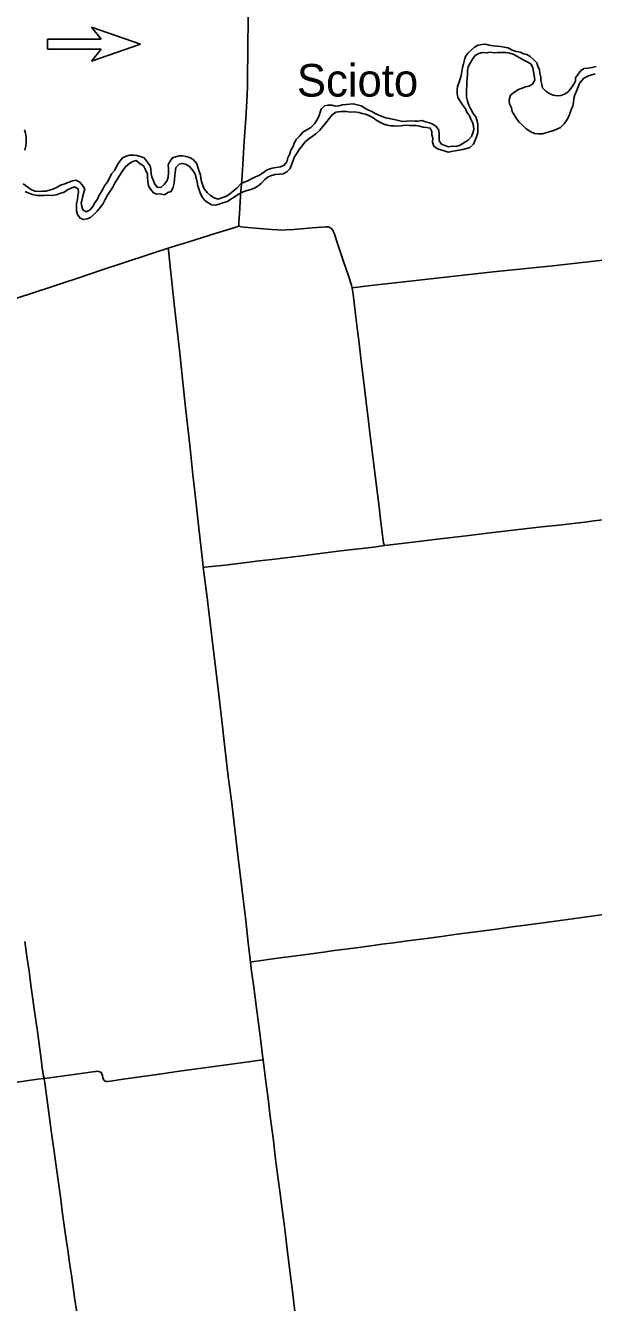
# Model space of a CAD drawing. Extents: x 0 to 680, y 0 to 440.
# Drawn here: x 190.2 to 248.2, y 233.7 to 364.2 of the extents above; entities that cross this region are included whole.
import ezdxf

# ---------------------------------------------------------------- set-up
doc = ezdxf.new("R2010")
doc.units = 0
for name, color, linetype in [('GM_X_County_Road', 7, 'Continuous'), ('GM_X_Major_River', 7, 'Continuous'), ('GM_X_Major_River_Text', 7, 'Continuous'), ('GM_X_Township_Road', 7, 'Continuous'), ('PM_P_Cells', 7, 'Continuous')]:
    doc.layers.add(name, color=color, linetype=linetype)

msp = doc.modelspace()

# ---------------------------------------------------------------- linework, layer by layer
at = {"layer": 'GM_X_County_Road'}
for points in [[(212.24, 347.98), (212.27, 348.35), (212.37, 349.99), (212.53, 352.39), (212.69, 354.68), (212.83, 357.08), (212.86, 358.06), (212.91, 362.44), (212.93, 364.41), (212.94, 365.18)], [(211.97, 343.69), (211.98, 344.09), (212.04, 344.97), (212.12, 346.17), (212.19, 347.26), (212.24, 347.98)], [(204.77, 341.45), (205.49, 341.69), (206.75, 342.07), (209.67, 342.98), (211.35, 343.49), (211.66, 343.59), (211.97, 343.69)], [(223.55, 337.4), (223.52, 337.53), (223.47, 337.68), (223.17, 338.62), (222.64, 340.17), (222.12, 341.73), (221.71, 342.97), (221.63, 343.17), (221.58, 343.27), (221.52, 343.36), (221.45, 343.44), (221.37, 343.5), (221.28, 343.55), (221.19, 343.59), (221.09, 343.61), (220.98, 343.63), (220.88, 343.63), (220.44, 343.59), (219.46, 343.51), (217.61, 343.36), (216.84, 343.31), (216.4, 343.3), (215.96, 343.32), (215.31, 343.36), (213.67, 343.5), (212.47, 343.6), (212.25, 343.63), (211.97, 343.69)], [(184.22, 333.58), (184.26, 333.59), (184.3, 333.6), (184.32, 333.62), (184.42, 333.68), (184.59, 333.82), (185.03, 334.15), (185.49, 334.45), (185.86, 334.68), (186.91, 335.27), (187.58, 335.63), (187.97, 335.83), (188.37, 336), (188.78, 336.15), (189.81, 336.51), (190.54, 336.75), (191.26, 336.99), (192.62, 337.43), (193.86, 337.84), (195.52, 338.39), (198.12, 339.25), (199.99, 339.87), (203.1, 340.9), (204.77, 341.45)], [(208.33, 308.82), (208.28, 309.25), (207.9, 312.84), (207.45, 316.87), (207.29, 318.28), (206.99, 321), (206.5, 325.46), (205.9, 331.01), (205.41, 335.46), (205, 339.27), (204.79, 341.23), (204.77, 341.45)], [(223.55, 337.4), (223.83, 337.44), (225.46, 337.64), (230.35, 338.19), (237.96, 339.02), (244.06, 339.65), (249.17, 340.21), (250.6, 340.37)], [(226.87, 311.05), (226.77, 311.33), (226.6, 312.63), (226.43, 314.04), (226.3, 315.02), (226.01, 317.4), (225.63, 320.44), (225.41, 322.29), (225.15, 324.35), (224.95, 325.98), (224.74, 327.71), (224.48, 329.89), (224.26, 331.73), (224.1, 333.03), (223.91, 334.66), (223.66, 336.73), (223.6, 337.16), (223.56, 337.37), (223.55, 337.4)], [(226.87, 311.05), (229.8, 311.41), (230.34, 311.47), (230.88, 311.53), (231.97, 311.67), (235.22, 312.06), (237.37, 312.32), (240.87, 312.73), (242.94, 312.96), (244.68, 313.16), (246.41, 313.36), (247.34, 313.46), (248.26, 313.57), (251.09, 313.89), (252.82, 314.1), (253.56, 314.18)], [(208.33, 308.82), (208.52, 308.84), (208.84, 308.87), (210.58, 309.06), (211.67, 309.2), (212.75, 309.33), (214.06, 309.49), (215.36, 309.65), (218.72, 310.06), (220.79, 310.32), (222.41, 310.51), (225.78, 310.91), (226.87, 311.05)], [(213.18, 268.5), (212.94, 270.47), (212.69, 272.75), (212.44, 274.68), (211.87, 279.42), (211.39, 283.54), (211.25, 284.74), (210.9, 287.45), (210.42, 291.62), (210.3, 292.61), (209.78, 296.98), (209.08, 302.85), (208.73, 305.74), (208.42, 308.06), (208.33, 308.82)], [(213.18, 268.5), (213.5, 268.55), (214.04, 268.63), (215.45, 268.82), (216.75, 268.99), (219.13, 269.32), (220.86, 269.55), (221.73, 269.67), (222.6, 269.79), (224.22, 270), (225.95, 270.24), (226.6, 270.33), (227.79, 270.48), (229.2, 270.66), (231.15, 270.91), (232.45, 271.09), (234.29, 271.34), (235.92, 271.56), (238.3, 271.88), (239.92, 272.1), (241.01, 272.25), (243.06, 272.52), (244.58, 272.72), (247.07, 273.06), (249.99, 273.45)], [(214.45, 258.52), (214.39, 258.96), (214.14, 260.96), (213.7, 264.29), (213.53, 265.69), (213.28, 267.59), (213.18, 268.5)], [(192.07, 256.61), (192.64, 256.69), (194.6, 256.94), (196.33, 257.18), (197.31, 257.33), (197.41, 257.34), (197.53, 257.35), (197.65, 257.33), (197.76, 257.3), (197.86, 257.24), (197.94, 257.16), (197.99, 257.06), (198.03, 256.95), (198.09, 256.63), (198.13, 256.53), (198.18, 256.44), (198.25, 256.37), (198.34, 256.33), (198.44, 256.31), (198.54, 256.31), (198.87, 256.35), (200.16, 256.55), (201.9, 256.78), (203.63, 257.02), (205.69, 257.31), (208.95, 257.76), (212.96, 258.31), (214.15, 258.48), (214.45, 258.52)], [(218.73, 224.62), (218.7, 224.88), (218.22, 228.68), (217.91, 231.07), (217.41, 235.14), (217.28, 236.17), (216.98, 238.6), (216.66, 241.2), (216.47, 242.75), (216.3, 244.05), (216.15, 245.11), (215.96, 246.55), (215.7, 248.65), (215.5, 250.29), (215.19, 252.71), (214.96, 254.56), (214.7, 256.54), (214.45, 258.52)], [(188.85, 256.17), (191.45, 256.53), (192.07, 256.61)]]:
    msp.add_lwpolyline(points, dxfattribs=at)
at = {"layer": 'GM_X_Major_River'}
for points in [[(238.35, 362.08), (237.97, 362.12), (237.54, 362.2), (237.17, 362.28), (236.82, 362.25), (236.43, 362.17), (236.04, 361.97), (235.71, 361.68), (235.37, 361.38), (235.13, 361.03), (235.02, 360.67), (234.92, 360.28), (234.82, 359.92), (234.75, 359.49), (234.7, 359.08), (234.5, 358.39), (234.32, 357.96), (234.28, 357.62), (234.28, 357.23), (234.34, 356.83), (234.58, 356.48), (234.83, 356.08), (235.13, 355.69), (235.27, 355.34), (235.56, 354.96), (235.67, 354.63), (235.85, 354.29), (235.95, 353.95), (235.97, 353.58), (235.9, 353.22), (235.76, 352.87), (235.42, 352.48), (234.95, 352.21), (234.6, 351.96), (234.17, 351.83), (233.77, 351.85), (233.39, 351.8), (233.02, 351.94), (232.68, 352.07), (232.43, 352.41), (232.44, 352.77), (232.45, 353.1), (232.41, 353.5), (232.13, 353.88), (231.79, 354.1), (231.45, 354.26), (231.06, 354.36), (230.7, 354.48), (230.3, 354.42), (229.97, 354.43), (229.51, 354.45), (229.1, 354.43), (228.7, 354.38), (228.3, 354.48), (227.86, 354.58), (227.35, 354.7), (227, 354.77), (226.62, 354.9), (226.28, 355.04), (225.92, 355.19), (225.58, 355.41), (225.23, 355.56), (224.85, 355.74), (224.48, 355.97), (224.05, 356.09), (223.65, 356.19), (223.29, 356.15), (222.95, 356.13), (222.55, 356.1), (222.18, 356), (221.84, 355.96), (221.48, 356.04), (221.09, 356.06), (220.73, 355.98), (220.4, 355.64), (220.14, 354.88), (219.96, 354.51), (219.72, 354.14), (219.32, 353.76), (218.93, 353.55), (218.51, 353.3), (218.21, 352.92), (217.87, 352.59), (217.62, 352.18), (217.52, 351.82), (217.28, 351.45), (217.2, 351.09), (216.98, 350.66), (216.88, 350.28), (216.62, 349.94), (216.22, 349.75), (215.79, 349.69), (215.39, 349.63), (214.88, 349.46), (214.38, 349.1), (214.02, 348.87), (213.68, 348.72), (213.26, 348.53), (212.9, 348.32), (212.52, 348.2), (212.13, 347.97)], [(229.37, 353.98), (230.08, 353.97), (230.43, 353.9), (230.81, 353.81), (231.16, 353.79), (231.54, 353.72), (231.68, 353.37), (231.71, 353.02), (231.79, 352.69), (231.76, 352.27), (231.9, 351.88), (232.26, 351.61), (232.95, 351.38), (233.37, 351.24), (233.71, 351.32), (234.07, 351.38), (234.44, 351.45), (234.85, 351.53), (235.23, 351.63), (235.58, 351.74), (235.94, 352.06), (236.13, 352.47), (236.27, 352.83), (236.41, 353.24), (236.4, 353.65), (236.38, 354.07), (236.32, 354.43), (236.19, 354.86), (235.93, 355.21), (235.66, 355.71), (235.48, 356.05), (235.34, 356.48), (235.24, 356.87), (235.23, 357.21), (235.25, 357.68), (235.26, 358.03), (235.28, 358.36), (235.3, 358.78), (235.33, 359.2), (235.34, 359.61), (235.42, 359.96), (235.6, 360.36), (235.85, 360.77), (236.14, 361.13), (236.5, 361.32), (236.88, 361.44), (237.33, 361.4), (237.66, 361.47), (238.06, 361.41), (238.4, 361.44), (238.87, 361.45), (239.25, 361.43), (239.65, 361.37), (240, 361.25), (240.37, 361.05), (240.79, 360.81), (241.16, 360.62), (241.52, 360.45), (241.86, 360.23), (242.03, 359.86), (242.08, 359.51), (242.15, 359.12), (242.22, 358.61), (241.98, 358.21), (241.61, 358.01), (241.28, 357.92), (240.93, 357.8), (240.55, 357.66), (240.19, 357.43), (239.74, 357.07), (239.6, 356.61), (239.63, 356.19), (239.83, 355.78), (239.9, 355.4), (240.12, 355.06), (240.32, 354.71), (240.62, 354.32), (241, 353.97), (241.35, 353.64), (241.8, 353.34), (242.2, 353.17), (242.59, 353.14), (243, 353.13), (243.36, 353.23), (243.79, 353.37), (244.17, 353.47), (244.52, 353.64), (244.85, 353.79), (245.22, 354.14), (245.45, 354.48), (245.65, 354.84), (245.81, 355.22), (245.92, 355.58), (246.09, 355.98), (246.18, 356.34), (246.21, 356.73), (246.3, 357.1), (246.48, 357.5), (246.64, 357.92), (246.82, 358.33), (247.21, 358.8)], [(248.47, 359.99), (248.05, 359.89), (247.64, 359.83), (247.26, 359.8), (246.92, 359.58), (246.66, 359.21), (246.39, 358.84), (246.37, 358.5), (246.13, 358.1), (245.91, 357.75), (245.59, 357.38), (245.26, 357.17), (244.87, 357.03), (244.49, 357.01), (244.11, 357.06), (243.76, 357.22), (243.33, 357.5), (243.02, 357.83), (242.94, 358.17), (242.82, 358.57), (242.82, 358.91), (242.74, 359.31), (242.69, 359.66), (242.53, 360.04), (242.41, 360.37), (242.1, 360.72), (241.76, 361.02), (241.41, 361.23), (241.07, 361.3), (240.71, 361.48), (240.32, 361.54), (239.9, 361.68), (239.49, 361.9), (239.07, 361.98), (238.7, 362.04), (238.35, 362.08)], [(247.21, 358.8), (247.7, 359.05), (248.05, 359.17), (248.4, 359.24)], [(198.55, 346.87), (198.81, 347.27), (199.09, 347.69), (199.35, 348.15), (199.58, 348.54), (199.8, 348.91), (200.03, 349.26), (200.4, 349.75), (200.82, 350.12), (201.16, 350.29), (201.49, 350.39), (201.88, 350.06), (202.22, 349.84), (202.43, 349.45), (202.63, 349.02), (202.65, 348.66), (202.69, 348.24), (202.75, 347.82), (202.95, 347.48), (203.24, 347.09), (203.59, 346.97), (203.93, 346.99), (204.37, 346.91), (204.71, 347.14), (205.06, 347.24), (205.28, 347.68), (205.38, 348.09), (205.41, 348.49), (205.47, 349.19), (205.55, 349.69), (205.89, 350.02), (206.23, 350.1), (206.61, 350), (206.97, 349.77), (207.27, 349.37), (207.5, 349.01), (207.62, 348.62), (207.71, 348.19), (207.79, 347.83), (207.88, 347.49), (208.02, 347.1), (208.21, 346.71), (208.5, 346.32), (208.85, 346.07), (209.23, 345.87), (209.58, 345.83), (209.98, 345.93), (210.34, 346.06), (210.81, 346.21), (211.17, 346.45), (211.51, 346.64), (211.94, 346.97), (212.43, 347.2), (212.82, 347.33), (213.21, 347.43), (213.58, 347.56), (213.96, 347.82), (214.3, 348.07), (214.62, 348.46), (214.96, 348.74), (215.3, 348.88), (215.69, 348.97), (216.12, 349), (216.5, 349.05), (216.87, 349.24), (217.22, 349.58), (217.37, 349.97), (217.5, 350.33), (217.67, 350.77), (217.93, 351.18), (218.15, 351.52), (218.42, 351.88), (218.76, 352.3), (219.14, 352.6), (219.48, 352.85), (219.85, 353.11), (220.23, 353.45), (220.55, 353.87), (220.86, 354.26), (221.24, 354.72), (221.51, 355.07), (221.89, 355.33), (222.44, 355.42), (222.93, 355.4), (223.39, 355.35), (223.8, 355.36), (224.23, 355.3), (224.57, 355.22), (224.93, 355.12), (225.33, 354.96), (225.69, 354.76), (226.07, 354.5), (226.44, 354.27), (226.78, 354.1), (227.13, 354.01), (227.49, 353.95), (227.85, 353.93), (228.18, 353.92), (228.57, 353.94), (229.01, 354.01), (229.37, 353.98)], [(190.12, 351.46), (190.2, 351.9), (190.25, 352.34), (190.24, 352.78), (190.19, 353.18), (190.08, 353.52)], [(212.13, 347.97), (211.77, 347.57), (211.4, 347.26), (211.05, 347), (210.7, 346.76), (210.24, 346.57), (209.85, 346.44), (209.47, 346.57), (209.08, 346.83), (208.74, 347.13), (208.44, 347.5), (208.29, 347.86), (208.16, 348.24), (208.1, 348.57), (208.05, 348.93), (207.92, 349.28), (207.8, 349.71), (207.67, 350.07), (207.38, 350.44), (207.02, 350.66), (206.59, 350.81), (206.21, 350.89), (205.87, 350.88), (205.52, 350.78), (205.18, 350.69), (204.94, 350.29), (204.77, 349.95), (204.79, 349.56), (204.78, 349.13), (204.74, 348.71), (204.65, 348.36), (204.39, 347.99), (204.04, 347.67), (203.68, 347.64), (203.39, 347.98), (203.25, 348.32), (203.07, 348.72), (203.03, 349.09), (202.99, 349.54), (202.91, 349.87), (202.6, 350.26), (202.3, 350.67), (201.93, 350.8), (201.56, 350.9), (201.2, 350.94), (200.85, 350.95), (200.47, 350.83), (200.1, 350.67), (199.72, 350.21), (199.5, 349.86), (199.3, 349.42), (198.98, 349.04), (198.75, 348.6), (198.55, 348.23), (198.25, 347.81), (198.03, 347.39), (197.68, 346.8), (197.52, 346.46), (197.26, 346.06), (197.07, 345.7), (196.77, 345.35), (196.39, 345.17), (196.04, 345.36), (195.93, 345.7), (195.87, 346.06), (195.96, 346.42), (196.05, 346.78), (196.14, 347.12), (196.23, 347.5), (196.02, 347.83), (195.74, 348.19), (195.33, 348.39), (194.99, 348.33), (194.53, 348.15), (194.09, 348), (193.75, 347.87), (193.41, 347.66), (192.97, 347.48), (192.63, 347.37), (192.27, 347.27), (191.91, 347.27), (191.56, 347.22), (191.18, 347.27), (190.78, 347.42), (189.93, 348.01)], [(190.15, 347.22), (190.53, 347.08), (190.9, 346.93), (191.34, 346.83), (191.73, 346.81), (192.09, 346.84), (192.51, 346.87), (192.95, 346.84), (193.31, 346.9), (193.7, 347.02), (194.11, 347.17), (194.46, 347.4), (194.83, 347.59), (195.19, 347.7), (195.55, 347.52), (195.58, 347.16), (195.52, 346.8), (195.49, 346.42), (195.39, 345.99), (195.37, 345.65), (195.38, 345.25), (195.49, 344.89), (195.76, 344.51), (196.11, 344.36), (196.47, 344.43), (196.81, 344.57), (197.17, 344.9), (197.51, 345.22), (197.85, 345.64), (198.12, 346.01), (198.32, 346.42), (198.55, 346.87)]]:
    msp.add_lwpolyline(points, dxfattribs=at)
at = {"layer": 'GM_X_Township_Road'}
for points in [[(192.07, 256.61), (192.07, 256.66), (192.03, 256.85), (191.89, 257.71), (191.78, 258.58), (191.39, 261.4), (191.16, 263.02), (190.73, 266.16), (190.54, 267.57), (190.32, 269.08), (190.11, 270.6)], [(195.88, 229.33), (195.86, 229.48), (195.75, 230.34), (195.65, 230.99), (195.54, 231.86), (195.38, 232.94), (195.19, 234.24), (194.86, 236.51), (194.77, 237.14), (194.65, 238.01), (194.53, 238.88), (194.3, 240.41), (193.97, 242.79), (193.74, 244.52), (193.57, 245.71), (193.3, 247.66), (193.06, 249.4), (192.83, 251.02), (192.48, 253.62), (192.17, 255.9), (192.07, 256.61)]]:
    msp.add_lwpolyline(points, dxfattribs=at)
at = {"layer": 'PM_P_Cells'}
for p, q in [((197.91, 362.79), (196.91, 364.03)), ((196.91, 364.03), (201.91, 362.29)), ((192.41, 361.79), (192.41, 362.79)), ((192.41, 362.79), (197.91, 362.79)), ((192.41, 362.29), (192.41, 362.29)), ((197.91, 361.79), (192.41, 361.79)), ((201.91, 362.29), (196.91, 360.55)), ((196.91, 360.55), (197.91, 361.79)), ((201.91, 362.29), (201.91, 362.29))]:
    msp.add_line(p, q, dxfattribs=at)

# ---------------------------------------------------------------- texts
at = {"layer": 'GM_X_Major_River_Text'}
msp.add_text('Scioto', height=3.334, rotation=0.0218, dxfattribs=at).set_placement((217.91, 356.93))

doc.saveas('drawing.dxf')
